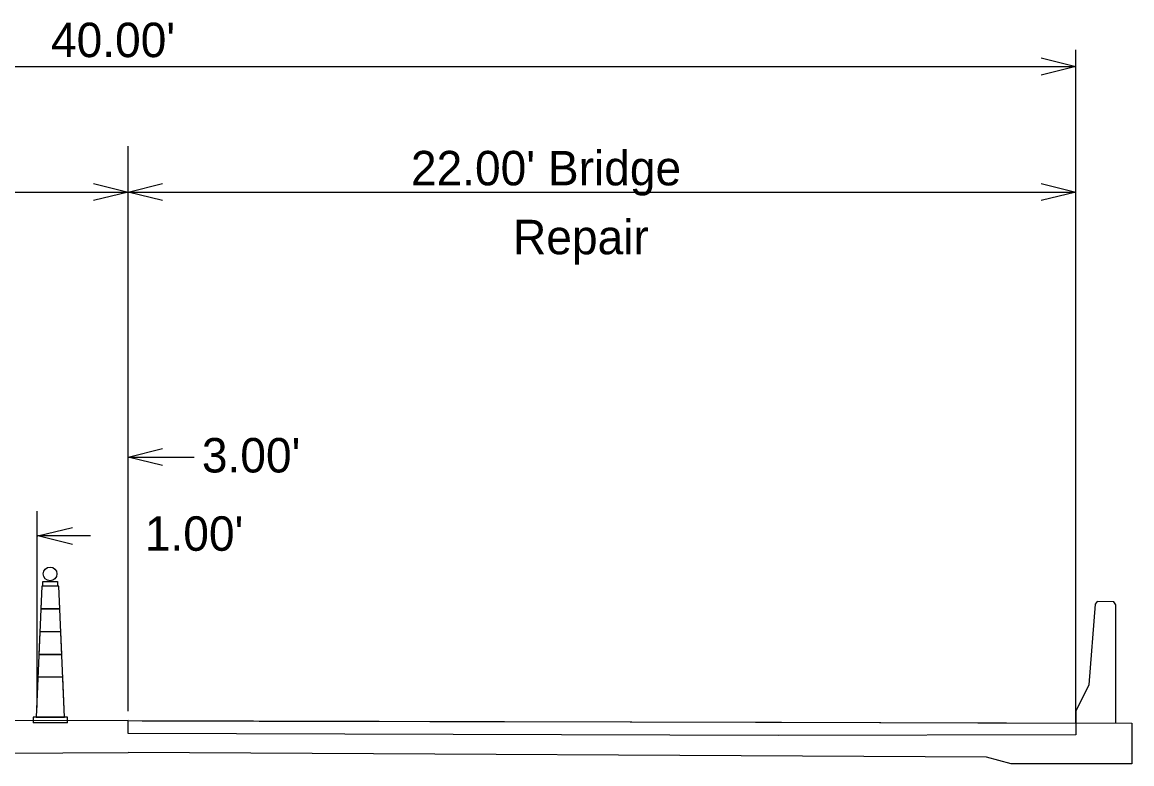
# Model space of a CAD drawing. Extents: x 8410 to 81668, y 7924 to 12712.
# Drawn here: x 9001 to 9732, y 8470 to 8959 of the extents above; entities that cross this region are included whole.
import ezdxf

# ---------------------------------------------------------------- set-up
doc = ezdxf.new("R2010")
doc.units = 0
for name, color, linetype in [('dsnCellElements', 7, 'Continuous'), ('Level 2', 7, 'Continuous'), ('Level 3', 7, 'Continuous')]:
    doc.layers.add(name, color=color, linetype=linetype)

msp = doc.modelspace()

# ---------------------------------------------------------------- linework, layer by layer
at = {"layer": 'dsnCellElements'}
for p, q in [((9013.91, 8586.99), (9010.16, 8500.74)), ((9013.91, 8586.99), (9013.26, 8571.99)), ((9025.16, 8586.99), (9013.91, 8586.99)), ((9025.16, 8586.99), (9013.91, 8586.99)), ((9028.91, 8500.74), (9025.16, 8586.99)), ((9025.81, 8571.99), (9025.16, 8586.99)), ((9025.81, 8571.99), (9013.26, 8571.99)), ((9013.26, 8571.99), (9025.81, 8571.99)), ((9012.61, 8556.99), (9011.95, 8541.99)), ((9026.47, 8556.99), (9012.61, 8556.99)), ((9026.47, 8556.99), (9012.61, 8556.99)), ((9027.12, 8541.99), (9026.47, 8556.99)), ((9027.12, 8541.99), (9011.95, 8541.99)), ((9011.95, 8541.99), (9027.12, 8541.99)), ((9011.3, 8526.99), (9010.16, 8500.74)), ((9027.77, 8526.99), (9011.3, 8526.99)), ((9027.77, 8526.99), (9011.3, 8526.99)), ((9028.91, 8500.74), (9027.77, 8526.99)), ((9030.79, 8500.74), (9008.29, 8500.74)), ((9008.29, 8500.74), (9008.29, 8496.99)), ((9030.79, 8496.99), (9008.29, 8496.99)), ((9010.16, 8500.74), (9028.91, 8500.74)), ((9030.79, 8496.99), (9030.79, 8500.74))]:
    msp.add_line(p, q, dxfattribs=at)
msp.add_lwpolyline([(9014.66, 8589.99), (9024.26, 8589.99), (9024.26, 8586.99), (9014.66, 8586.99)], close=True, dxfattribs=at)
msp.add_circle((9019.46, 8595.09), 4.5, dxfattribs=at)
at = {"layer": 'Level 2'}
for p, q in [((9695.1, 8496.79), (9695.1, 8940.41)), ((8446.51, 8929.48), (9695.1, 8929.48)), ((9070.8, 8504.58), (9070.8, 8876.93)), ((8446.51, 8846.77), (9070.8, 8846.77)), ((9070.8, 8846.77), (9695.1, 8846.77)), ((9070.8, 8672.12), (9114.25, 8672.12)), ((9010.99, 8507.13), (9010.99, 8636.55)), ((9046.1, 8620.1), (9011.41, 8620.1)), ((9707.86, 8575.07), (9703.69, 8522.04)), ((9709.26, 8576.91), (9707.86, 8575.07)), ((9720.09, 8576.66), (9709.26, 8576.91)), ((9721.44, 8574.76), (9720.09, 8576.66)), ((9721.44, 8496.72), (9721.44, 8574.76)), ((9703.69, 8522.04), (9695.18, 8504.73)), ((9695.18, 8504.73), (9695.1, 8496.79)), ((8505.29, 8474.39), (9070.8, 8477.31)), ((9636.32, 8474.39), (9070.8, 8477.31)), ((9652.54, 8469.94), (9636.32, 8474.39))]:
    msp.add_line(p, q, dxfattribs=at)
for points in [[(9672.39, 8935.16), (9695.1, 8929.48), (9672.39, 8923.81)], [(9048.1, 8852.45), (9070.8, 8846.77), (9048.1, 8841.09)], [(9093.51, 8841.09), (9070.8, 8846.77), (9093.51, 8852.45)], [(9672.39, 8852.45), (9695.1, 8846.77), (9672.39, 8841.09)], [(9093.51, 8666.45), (9070.8, 8672.12), (9093.51, 8677.8)], [(9034.12, 8614.42), (9011.41, 8620.1), (9034.12, 8625.77)], [(9732.02, 8496.69), (9732.02, 8469.94), (9652.54, 8469.94)]]:
    msp.add_lwpolyline(points, dxfattribs=at)
at = {"layer": 'Level 3'}
for p, q in [((9070.8, 8498.41), (8409.59, 8496.69)), ((9070.8, 8498.41), (9732.02, 8496.69)), ((9070.8, 8489.99), (9070.8, 8494.6)), ((9499.12, 8488.69), (9070.8, 8489.99))]:
    msp.add_line(p, q, dxfattribs=at)
for points in [[(9070.8, 8494.6), (9070.8, 8498.41), (9079.97, 8498.34), (9098.49, 8498.29), (9124.49, 8498.23), (9157.23, 8498.15), (9204.4, 8498.03), (9269.65, 8497.87), (9304.1, 8497.79), (9501.29, 8497.31)], [(9501.29, 8497.31), (9695.1, 8496.79), (9695.07, 8489.1), (9499.12, 8488.69)]]:
    msp.add_lwpolyline(points, dxfattribs=at)

# ---------------------------------------------------------------- texts
at = {"layer": 'Level 2'}
for s, height, p in [("40.00'", 22.709, (9020.01, 8935.65)), ("22.00' Bridge", 22.7091, (9257.13, 8851.17)), ('Repair', 22.709, (9324.37, 8805.76)), ("3.00'", 22.709, (9119.41, 8661.94)), ("1.00'", 22.709, (9081.83, 8610.34))]:
    msp.add_text(s, height=height, dxfattribs=at).set_placement(p)

doc.saveas('drawing.dxf')
